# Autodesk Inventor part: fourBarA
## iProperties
Created: 2008-10
Part Number: fourBarA
Document SubType Name: Modeling
Designer: Lochan
Density: 1 g/cm^3
Mass: 1.68267 g
Surface Area: 17.8111 cm^2
Volume: 1.68267 cm^3
Author: Lochan
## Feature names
1. Extrusion1
2. Hole1
